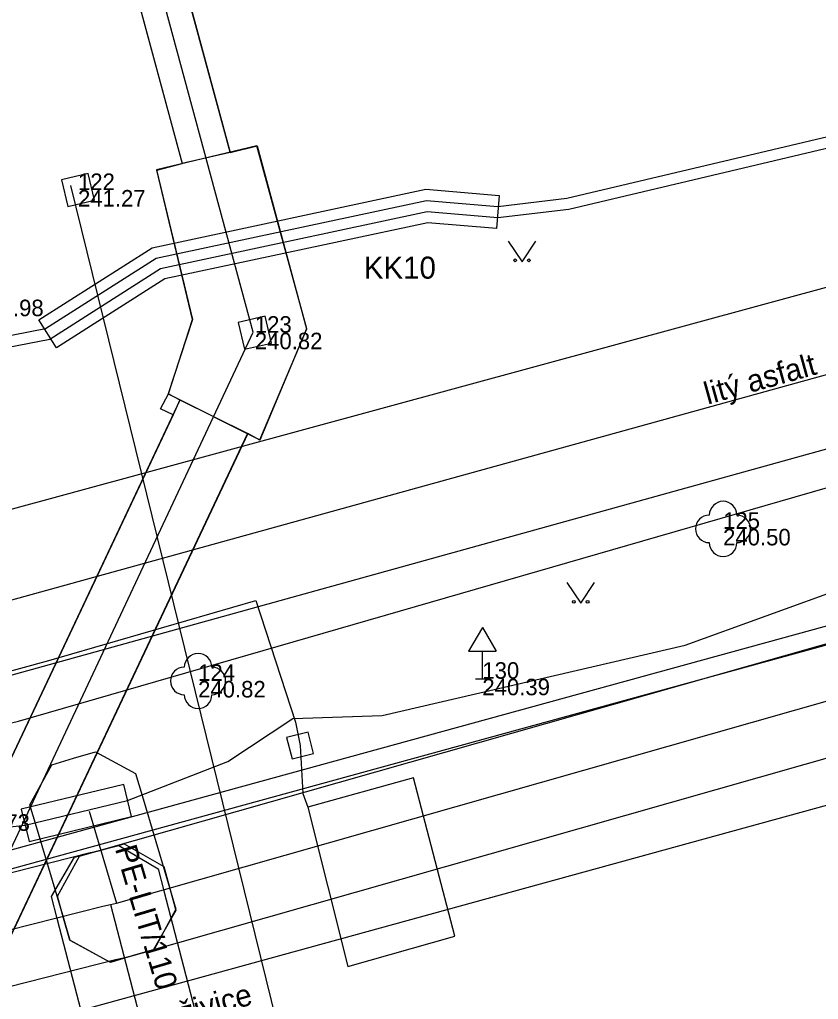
# Model space of a CAD drawing. Extents: x -599432 to -598680, y -1159407 to -1158632.
# Drawn here: x -598996.8 to -598982.3, y -1158877.11 to -1158859.33 of the extents above; entities that cross this region are included whole.
import ezdxf

# ---------------------------------------------------------------- set-up
doc = ezdxf.new("R2010")
doc.units = 0
for name, color, linetype in [('0004 VY - Body podrobné', 7, 'Continuous'), ('0005 VY - Body podrobné - čísla', 7, 'Continuous'), ('0006 VY - Body podrobné - výšky', 7, 'Continuous'), ('0027 ZA - Silnice_cesta zpevněná', 7, 'Continuous'), ('0030 ZA - Chodník', 7, 'Continuous'), ('0031 ZA - Ostatní rozhraní', 7, 'Continuous'), ('0032 TE - Popis povrchu', 7, 'Continuous'), ('0034 ZA - Kultury - značky', 7, 'Continuous'), ('0035 ZA - Strom - značka', 7, 'Continuous'), ('0062 ZA - Doprava - dopravní značky', 7, 'Continuous'), ('0080 ZA - BVK - vodovod - buňky', 7, 'Continuous'), ('0215 PV - BVK - vodovod - pitná přípojka', 7, 'Continuous'), ('0264 PV - TB - parovod mimo provoz', 7, 'Continuous'), ('0301 PV - RWE - popis', 7, 'Continuous'), ('0302 PV - RWE - NTL', 7, 'Continuous'), ('0303 PV - RWE - NTL přípojka', 7, 'Continuous'), ('0308 PV - RWE - ochranné pásmo', 7, 'Continuous'), ('0352 PV - EON - NN', 7, 'Continuous'), ('0354 PV - EON - VN', 7, 'Continuous'), ('0367 PV - EON - VN chránička', 7, 'Continuous'), ('0455 PV - O2 - kabel nezaměřený', 7, 'Continuous'), ('0456 PV - O2 - sítě s NN', 7, 'Continuous'), ('0457 PV - O2 - kabelovod', 7, 'Continuous'), ('0552 PV - NETBOX - vedení', 7, 'Continuous'), ('0553 PV - NETBOX - chranička', 7, 'Continuous'), ('0650 PV - BKOM - buňky', 7, 'Continuous'), ('0651 PV - BKOM - popis', 7, 'Continuous'), ('0652 PV - BKOM - kabely bez rozlišení', 7, 'Continuous'), ('0750 ZA - nerozlišené sítě - buňky', 7, 'Continuous')]:
    doc.layers.add(name, color=color, linetype=linetype)

msp = doc.modelspace()

# ---------------------------------------------------------------- linework, layer by layer
at = {"layer": '0004 VY - Body podrobné'}
for p, q in [((-598995.74, -1158862.42), (-598995.74, -1158862.42)), ((-598992.53, -1158865.01), (-598992.53, -1158865.01)), ((-598984.03, -1158868.57), (-598984.03, -1158868.57)), ((-598993.56, -1158871.33), (-598993.56, -1158871.33)), ((-598988.4, -1158871.29), (-598988.4, -1158871.29))]:
    msp.add_line(p, q, dxfattribs=at)
at = {"layer": '0027 ZA - Silnice_cesta zpevněná'}
msp.add_line((-598977.96, -1158869.18), (-599007.18, -1158877.21), dxfattribs=at)
at = {"layer": '0030 ZA - Chodník'}
for p, q in [((-598978.46, -1158863.18), (-599008.41, -1158871.34)), ((-598977.38, -1158865.8), (-599008.02, -1158874.3))]:
    msp.add_line(p, q, dxfattribs=at)
at = {"layer": '0031 ZA - Ostatní rozhraní'}
msp.add_line((-598977.872, -1158869.501), (-599007.092, -1158877.531), dxfattribs=at)
at = {"layer": '0034 ZA - Kultury - značky'}
for points in [[(-598987.93, -1158863.346), (-598987.68, -1158863.721), (-598987.43, -1158863.346)], [(-598986.864, -1158869.543), (-598986.614, -1158869.918), (-598986.364, -1158869.543)]]:
    msp.add_lwpolyline(points, dxfattribs=at)
for centre in [(-598987.805, -1158863.696), (-598987.555, -1158863.696), (-598986.739, -1158869.893), (-598986.489, -1158869.893)]:
    msp.add_circle(centre, 0.025, dxfattribs=at)
at = {"layer": '0035 ZA - Strom - značka'}
for centre in [(-598984.03, -1158868.57), (-598993.56, -1158871.33)]:
    msp.add_circle(centre, 0.00025, dxfattribs=at)
for centre, start, end in [((-598984.03, -1158868.32), 0, 180), ((-598984.28, -1158868.57), 90, 270), ((-598983.78, -1158868.57), 270, 90), ((-598984.03, -1158868.82), 180, 360), ((-598993.56, -1158871.08), 0, 180), ((-598993.81, -1158871.33), 90, 270), ((-598993.31, -1158871.33), 270, 90), ((-598993.56, -1158871.58), 180, 360)]:
    msp.add_arc(centre, 0.25, start, end, dxfattribs=at)
at = {"layer": '0062 ZA - Doprava - dopravní značky'}
for p, q in [((-598988.4, -1158870.357), (-598988.65, -1158870.79)), ((-598988.4, -1158870.357), (-598988.15, -1158870.79)), ((-598988.65, -1158870.79), (-598988.15, -1158870.79)), ((-598988.4, -1158871.29), (-598988.4, -1158870.79)), ((-598988.525, -1158871.29), (-598988.275, -1158871.29))]:
    msp.add_line(p, q, dxfattribs=at)
at = {"layer": '0080 ZA - BVK - vodovod - buňky'}
for p, q in [((-598995.553, -1158862.12), (-598996.04, -1158862.233)), ((-598996.04, -1158862.233), (-598995.927, -1158862.72)), ((-598995.44, -1158862.607), (-598995.553, -1158862.12)), ((-598995.927, -1158862.72), (-598995.44, -1158862.607))]:
    msp.add_line(p, q, dxfattribs=at)
at = {"layer": '0215 PV - BVK - vodovod - pitná přípojka'}
msp.add_lwpolyline([(-598990.256, -1158885.052), (-598990.376, -1158884.615), (-598990.455, -1158884.328), (-598995.872, -1158862.336)], dxfattribs=at)
at = {"layer": '0264 PV - TB - parovod mimo provoz'}
msp.add_line((-598964.206, -1158868.658), (-599015.807, -1158882.836), dxfattribs=at)
at = {"layer": '0302 PV - RWE - NTL'}
for points in [[(-598995.04, -1158875.36), (-598966.53, -1158867.25), (-598961.5, -1158865.92), (-598957.92, -1158864.98), (-598953.83, -1158863.9), (-598944.155, -1158861.035)], [(-598995.535, -1158873.691), (-598995.04, -1158875.36)], [(-599031.044, -1158884.383), (-598999.16, -1158876.4), (-598995.29, -1158875.42), (-598995.15, -1158875.39), (-598995.04, -1158875.36)]]:
    msp.add_lwpolyline(points, dxfattribs=at)
at = {"layer": '0303 PV - RWE - NTL přípojka'}
msp.add_lwpolyline([(-598995.15, -1158875.39), (-598984.16, -1158917.67), (-598984.11, -1158917.86)], dxfattribs=at)
at = {"layer": '0308 PV - RWE - ochranné pásmo'}
for points in [[(-598944.385, -1158860.06), (-598943.926, -1158862.01), (-598953.56, -1158864.863), (-598957.665, -1158865.947), (-598961.245, -1158866.887), (-598966.265, -1158868.214), (-598994.766, -1158876.322), (-598995.164, -1158876.435), (-598995.889, -1158876.032), (-598996.002, -1158875.634), (-598996.115, -1158875.236), (-598995.712, -1158874.511), (-598995.314, -1158874.398), (-598966.795, -1158866.286), (-598961.755, -1158864.953), (-598958.175, -1158864.013), (-598954.1, -1158862.937)], [(-598994.694, -1158873.01), (-598994.576, -1158873.407), (-598994.081, -1158875.076), (-598993.963, -1158875.473), (-598994.359, -1158876.201), (-598994.756, -1158876.319), (-598995.153, -1158876.437), (-598995.881, -1158876.041), (-598995.999, -1158875.644), (-598996.494, -1158873.975), (-598996.612, -1158873.578), (-598996.216, -1158872.85), (-598995.819, -1158872.732), (-598995.422, -1158872.614)], [(-599031.689, -1158883.514), (-599031.287, -1158883.413), (-598999.404, -1158875.43), (-598995.518, -1158874.446), (-598995.387, -1158874.418), (-598995.303, -1158874.395), (-598994.903, -1158874.286), (-598994.184, -1158874.697), (-598994.075, -1158875.097), (-598993.966, -1158875.497), (-598994.377, -1158876.216), (-598994.777, -1158876.325), (-598994.913, -1158876.362), (-598995.062, -1158876.394), (-598998.916, -1158877.37), (-599030.801, -1158885.353), (-599031.203, -1158885.454), (-599031.913, -1158885.028), (-599032.014, -1158884.626), (-599032.115, -1158884.224)], [(-598994.286, -1158874.737), (-598994.182, -1158875.138), (-598983.193, -1158917.417), (-598983.143, -1158917.606), (-598983.037, -1158918.007), (-598983.455, -1158918.722), (-598983.856, -1158918.827), (-598984.257, -1158918.933), (-598984.972, -1158918.515), (-598985.077, -1158918.114), (-598985.127, -1158917.923), (-598996.118, -1158875.642), (-598996.222, -1158875.241), (-598995.803, -1158874.526), (-598995.402, -1158874.422), (-598995.001, -1158874.318)]]:
    msp.add_lwpolyline(points, close=True, dxfattribs=at)
at = {"layer": '0352 PV - EON - NN'}
msp.add_lwpolyline([(-599021.682, -1158826.616), (-599018.026, -1158839.848), (-599017.168, -1158839.601), (-599017.124, -1158839.718), (-599017.057, -1158839.985), (-599017.919, -1158840.233), (-599016.234, -1158846.334), (-599013.125, -1158857.581), (-599012.296, -1158857.347), (-599012.256, -1158857.465), (-599012.187, -1158857.732), (-599013.017, -1158857.966), (-599008.822, -1158873.141), (-598963.861, -1158860.708)], dxfattribs=at)
at = {"layer": '0354 PV - EON - VN'}
for points in [[(-599068.426, -1158889.707), (-599062.435, -1158887.486), (-599057.559, -1158885.602), (-599053.514, -1158882.536), (-599048.468, -1158879.787), (-599040.575, -1158877.583), (-599039.069, -1158877.224), (-599035.277, -1158875.867), (-599021.599, -1158869.995), (-599019.639, -1158870.482), (-599018.747, -1158870.641), (-599017.491, -1158870.75), (-599015.995, -1158870.391), (-599015.549, -1158870.322), (-599008.216, -1158868.696), (-599005.678, -1158867.267), (-598998.773, -1158865.413), (-598996.328, -1158864.935), (-598994.319, -1158863.656), (-598989.416, -1158862.609), (-598988.122, -1158862.719), (-598986.867, -1158862.571), (-598978.725, -1158860.643), (-598971.459, -1158858.594)], [(-599068.354, -1158889.893), (-599062.365, -1158887.674), (-599057.461, -1158885.778), (-599053.406, -1158882.704), (-599048.392, -1158879.973), (-599040.525, -1158877.777), (-599039.011, -1158877.416), (-599035.203, -1158876.053), (-599021.581, -1158870.205), (-599019.681, -1158870.678), (-599018.773, -1158870.839), (-599017.509, -1158870.95), (-599015.965, -1158870.589), (-599015.511, -1158870.518), (-599008.144, -1158868.884), (-599005.602, -1158867.453), (-598998.727, -1158865.607), (-598996.252, -1158865.125), (-598994.241, -1158863.844), (-598989.404, -1158862.811), (-598988.118, -1158862.921), (-598986.833, -1158862.769), (-598978.675, -1158860.837), (-598971.401, -1158858.786)]]:
    msp.add_lwpolyline(points, dxfattribs=at)
at = {"layer": '0367 PV - EON - VN chránička'}
for p, q in [((-598994.396, -1158863.468), (-598989.429, -1158862.407)), ((-598989.429, -1158862.407), (-598988.095, -1158862.521)), ((-598988.095, -1158862.521), (-598988.145, -1158863.119)), ((-598989.391, -1158863.013), (-598994.164, -1158864.032)), ((-598988.145, -1158863.119), (-598989.391, -1158863.013)), ((-598996.451, -1158864.777), (-598994.396, -1158863.468)), ((-598994.164, -1158864.032), (-598996.129, -1158865.283)), ((-598996.129, -1158865.283), (-598996.451, -1158864.777))]:
    msp.add_line(p, q, dxfattribs=at)
at = {"layer": '0455 PV - O2 - kabel nezaměřený'}
for points in [[(-598992.56, -1158865), (-599016.04, -1158778.27), (-599016.64, -1158776.55)], [(-599011.61, -1158875.82), (-599007.59, -1158874.62), (-598996.82, -1158872.06), (-598955.03, -1158859.99), (-598940.58, -1158856.31), (-598931.77, -1158853.97)], [(-599004.95, -1158891.42), (-598992.56, -1158865)]]:
    msp.add_lwpolyline(points, dxfattribs=at)
at = {"layer": '0456 PV - O2 - sítě s NN'}
for points in [[(-598992.56, -1158865), (-599016.04, -1158778.27), (-599016.64, -1158776.55)], [(-599004.95, -1158891.42), (-598992.56, -1158865)]]:
    msp.add_lwpolyline(points, dxfattribs=at)
at = {"layer": '0457 PV - O2 - kabelovod'}
for points in [[(-599015.63, -1158778.14), (-598992.98, -1158861.74)], [(-599016.44, -1158778.41), (-598993.85, -1158861.94)], [(-598992.98, -1158861.74), (-598993.85, -1158861.94)], [(-598992.98, -1158861.74), (-598992.49, -1158861.62), (-598991.59, -1158864.94), (-598992.44, -1158866.96), (-598992.66, -1158866.84)], [(-598994.1, -1158866.12), (-598993.66, -1158864.77), (-598994.31, -1158862.06), (-598993.85, -1158861.94)], [(-598994.01, -1158866.5), (-598994.24, -1158866.39), (-598994.1, -1158866.12)], [(-598994.1, -1158866.12), (-598993.89, -1158866.23)], [(-598993.89, -1158866.23), (-598994.01, -1158866.5)], [(-598993.89, -1158866.23), (-598992.66, -1158866.84)], [(-598994.01, -1158866.5), (-599005.01, -1158889.8)], [(-598992.66, -1158866.84), (-599003.78, -1158890.39)]]:
    msp.add_lwpolyline(points, dxfattribs=at)
at = {"layer": '0552 PV - NETBOX - vedení'}
msp.add_lwpolyline([(-599007.05, -1158870.63), (-599005.73, -1158870.36), (-599005.1, -1158870.54), (-599001.99, -1158872.63), (-599000.99, -1158874.31), (-598999.99, -1158874.79), (-598997.8, -1158874.07), (-598996.7, -1158873.95), (-598994.84, -1158873.5), (-598993.019, -1158872.79), (-598991.84, -1158872.01), (-598990.22, -1158871.96), (-598984.72, -1158870.68), (-598978.84, -1158868.55), (-598975.909, -1158867.89)], dxfattribs=at)
at = {"layer": '0553 PV - NETBOX - chranička'}
msp.add_lwpolyline([(-598996.771, -1158873.658), (-598996.629, -1158874.242), (-598994.769, -1158873.792), (-598994.911, -1158873.208)], close=True, dxfattribs=at)
at = {"layer": '0650 PV - BKOM - buňky'}
msp.add_lwpolyline([(-598991.953, -1158872.355), (-598991.855, -1158872.743), (-598991.467, -1158872.645), (-598991.565, -1158872.257)], close=True, dxfattribs=at)
at = {"layer": '0652 PV - BKOM - kabely bez rozlišení'}
for p, q in [((-598992.98, -1158861.736), (-599015.628, -1158778.139)), ((-598993.846, -1158861.943), (-599016.444, -1158778.408)), ((-599005.013, -1158889.795), (-598993.885, -1158866.227)), ((-599003.777, -1158890.385), (-598992.662, -1158866.844))]:
    msp.add_line(p, q, dxfattribs=at)
msp.add_lwpolyline([(-598994.101, -1158866.119), (-598992.439, -1158866.957), (-598991.588, -1158864.939), (-598992.494, -1158861.62), (-598994.313, -1158862.055), (-598993.664, -1158864.769)], close=True, dxfattribs=at)
for points in [[(-599006.875, -1158874.155), (-599006.35, -1158873.72), (-598996.27, -1158870.96), (-598992.51, -1158869.87), (-598991.79, -1158872.08), (-598991.71, -1158872.5)], [(-598991.71, -1158872.5), (-598991.66, -1158873.37), (-598991.57, -1158873.62), (-598990.84, -1158876.51), (-598988.9, -1158875.96), (-598989.65, -1158873.09), (-598991.57, -1158873.62)]]:
    msp.add_lwpolyline(points, dxfattribs=at)
at = {"layer": '0750 ZA - nerozlišené sítě - buňky'}
for p, q in [((-598992.343, -1158864.71), (-598992.83, -1158864.823)), ((-598992.23, -1158865.197), (-598992.343, -1158864.71)), ((-598992.83, -1158864.823), (-598992.717, -1158865.31)), ((-598992.717, -1158865.31), (-598992.23, -1158865.197))]:
    msp.add_line(p, q, dxfattribs=at)

# ---------------------------------------------------------------- texts
at = {"layer": '0005 VY - Body podrobné - čísla'}
for s, p in [('122', (-598995.74, -1158862.42)), ('123', (-598992.53, -1158865.01)), ('125', (-598984.03, -1158868.57)), ('130', (-598988.4, -1158871.29)), ('124', (-598993.56, -1158871.33))]:
    msp.add_text(s, height=0.3, dxfattribs=at).set_placement(p)
at = {"layer": '0006 VY - Body podrobné - výšky'}
for s, p in [('241.27', (-598995.74, -1158862.72)), ('240.98', (-598997.59, -1158864.71)), ('240.82', (-598992.53, -1158865.31)), ('240.50', (-598984.03, -1158868.87)), ('240.82', (-598993.56, -1158871.63)), ('240.39', (-598988.4, -1158871.59)), ('240.73', (-598997.84, -1158874.05))]:
    msp.add_text(s, height=0.3, dxfattribs=at).set_placement(p)
at = {"layer": '0032 TE - Popis povrchu'}
for s, rotation, p in [('litý asfalt', 15.5048, (-598984.311, -1158866.316)), ('živice', 15.5236, (-598993.836, -1158877.553))]:
    msp.add_text(s, height=0.4, rotation=rotation, dxfattribs=at).set_placement(p)
at = {"layer": '0301 PV - RWE - popis'}
msp.add_text('PE-LIT/110', height=0.4, rotation=286.5196, dxfattribs=at).set_placement((-598995.073, -1158874.373))
at = {"layer": '0651 PV - BKOM - popis'}
msp.add_text('KK10', height=0.4, dxfattribs=at).set_placement((-598990.552, -1158864.029))

doc.saveas('drawing.dxf')
